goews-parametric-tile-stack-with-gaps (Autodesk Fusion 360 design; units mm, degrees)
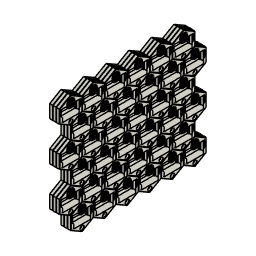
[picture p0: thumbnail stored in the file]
parameter "width" = 42
parameter "height" = 48.497
parameter "offset" = 36.373
parameter "DoubleVerticalDistance" = 72.746
parameter "StackGap" = 0.2
parameter "Tileheight" = 6
sketch "Reference" plane through (0, 0, 0) normal (1, 0, 0) x axis (0, 1, 0)
  line L1 (-18, -1.6244) -> (-15.5, -4.1244)
  line L2 (-18, 9.8756) -> (-18, -1.6244)
  line L3 (-8.5448, 9.8756) -> (-18, 9.8756)
  line L4 (18, 9.8756) -> (8.5448, 9.8756)
  line L5 (18, -1.6244) -> (18, 9.8756)
  line L6 (15.5, -4.1244) -> (18, -1.6244)
  line L7 (15.5, -12.1244) -> (15.5, -4.1244)
  line L8 (-15.5, -12.1244) -> (15.5, -12.1244)
  line L9 (-15.5, -4.1244) -> (-15.5, -12.1244)
  line L10 (20.5, 11.8357) -> (20.5, -11.8357)
  line L11 (0, 23.6714) -> (20.5, 11.8357)
  line L12 (-20.5, 11.8357) -> (0, 23.6714)
  line L13 (-20.5, -11.8357) -> (-20.5, 11.8357)
  line L14 (0, -23.6714) -> (-20.5, -11.8357)
  line L15 (20.5, -11.8357) -> (0, -23.6714)
  circle C1 centre (0, 12.7017) radius 7.1612
  arc A1 centre (0, 12.7017) radius 9 clockwise from (8.5448, 9.8756) to (-8.5448, 9.8756)
  circle C2 centre (0, -18.2487) radius 4
  point P22 (-42, 24.2487)
  point P27 (-21, -12.1244)
  point P20 (0, -24.2487)
  point P23 (-21, 60.6218)
  point P21 (21, -12.1244)
  point P25 (0, 48.4974)
  point P28 (0, 24.2487)
  point P26 (21, 12.1244)
  dimension "d7" distance P22 P27 = 36.3731
  dimension "d8" distance P20 P23 = 84.8705
  dimension "d9" distance P21 P23 = 84
  dimension "d10" distance P21 P22 = 63
  dimension "d11" distance P20 P25 = 72.7461
  dimension "d17" distance P21 P27 = 42
  dimension "d18" distance P20 P28 = 48.4974
  dimension "d19" distance P23 P28 = 36.3731
  dimension "d24" distance P20 P26 = 36.3731
copy_paste_bodies "CutPasteBodies"
sketch "patch" plane through (-6, 0, 0) normal (-1, 0, 0) x axis (0, -1, 0)
  line L1 (3, 25.9808) -> (16.0118, 18.4684)
  line L2 (3, 26.0061) -> (3, 25.9808)
  line L3 (39, 26.0061) -> (3, 26.0061)
  line L4 (39, 25.9808) -> (39, 26.0061)
  line L5 (25.9882, 18.4684) -> (39, 25.9808)
  curve K1 (16.3334, 53.0977) -> (19.1178, 42.0472)
  curve K2 (22.8822, 42.0472) -> (25.6666, 53.0977)
  line L6 (0, 24.2487) -> (0, 48.4974)
  line L7 (21, 12.1244) -> (0, 24.2487)
  line L8 (42, 24.2487) -> (21, 12.1244)
  line L9 (42, 48.4974) -> (42, 24.2487)
  line L10 (21, 60.6218) -> (42, 48.4974)
  line L11 (0, 48.4974) -> (21, 60.6218)
  line L12 (7.5, 46.2487) -> (7.5, 30.2487)
  line L13 (12.4552, 46.2487) -> (7.5, 46.2487)
  line L14 (34.5, 46.2487) -> (29.5448, 46.2487)
  line L15 (34.5, 30.2487) -> (34.5, 46.2487)
  line L16 (7.5, 30.2487) -> (34.5, 30.2487)
  line L17 (9.8586, 52.0614) -> (11.841, 52.0614)
  line L18 (9.8586, 48.8529) -> (9.8586, 52.0614)
  line L19 (11.841, 48.8529) -> (9.8586, 48.8529)
  line L20 (11.841, 52.0614) -> (11.841, 48.8529)
  line L21 (32.2218, 52.0614) -> (29.7148, 52.0614)
  line L22 (32.2218, 48.4173) -> (32.2218, 52.0614)
  line L23 (29.7148, 48.4173) -> (32.2218, 48.4173)
  line L24 (29.7148, 52.0614) -> (29.7148, 48.4173)
  arc A1 centre (21, 18.1244) radius 5 clockwise from (16.0118, 18.4684) to (25.9882, 18.4684)
  arc A2 centre (21, 49.0748) radius 6.1612 clockwise from (16.3334, 53.0977) to (25.6666, 53.0977)
  arc A3 centre (21, 49.0748) radius 7.2753 clockwise from (22.8822, 42.0472) to (19.1178, 42.0472)
  circle C1 centre (21, 18.1244) radius 2
  arc A4 centre (21, 49.0748) radius 9 clockwise from (29.5448, 46.2487) to (12.4552, 46.2487)
  horizontal L17
  vertical L18
  horizontal L19
  vertical L20
  horizontal L21
  vertical L22
  horizontal L23
  vertical L24
extrude "Extrude1" add sketch "patch" profile of L17 L18 L19 L20 L21 L22 L23 L24 against normal blind 6
copy_paste_bodies "CopyPasteBodies3"
copy_paste_bodies "CopyPasteBodies4"
move "Move3"
align "Align1"
move "Move2"
combine "Combine3" bodies "Hex (1)"
rectangular_pattern "R-Pattern3" countU 3 (= "VerticalQTY / 2") uSpaceDistance 72.746 vSpaceDistance -42 bodies "Hex (10)", "Hex (11)", "Hex (8)", "Hex (14)", "Hex (15)", "Hex (1)", "Hex (18)", "Hex (19)"
combine "Combine6" bodies "Hex (22)", "Hex (2)", "Hex (27)", "Hex (18)", "Hex (31)", "Hex (11)", "Hex (10)", "Hex (8)"
rectangular_pattern "R-Pattern4" uSpaceDistance 6.2 (= "Tileheight + StackGap") vSpaceDistance 0 bodies "Hex (1)", "Hex (2)"
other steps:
base_feature "Base Feature1" bodies "Hex"
base_feature "Base Feature3" bodies "Hex (1)"
base_feature "Base Feature4" bodies "Hex (1) (1)"
named bodies: "Hex", "Hex (1)", "Hex (8)", "Hex (1) (1)", "Hex (2)", "Hex (3)", "Hex (4)", "Hex (10)", "Hex (11)", "Hex (14)", "Hex (15)", "Hex (18)", "Hex (19)", "Hex (22)", "Hex (23)", "Hex (26)", "Hex (27)", "Hex (30)", "Hex (31)"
